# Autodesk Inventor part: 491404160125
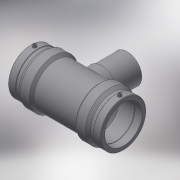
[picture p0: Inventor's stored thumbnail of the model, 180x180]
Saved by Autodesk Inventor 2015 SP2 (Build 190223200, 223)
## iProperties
Created: 2017-06
Part Number: 491404160125
Material: Generic
Description: PLASSON REDUCING TEE 160x125x160
Document SubType Name: Modeling
Designer: KIM
Mass: 5000.41 g
Surface Area: 5471.45 cm^2
Volume: 5000.41 cm^3
Density: 1 g/cm^3
Appearance: Default
Author: KIM
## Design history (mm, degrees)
derived "491404.ipt"
feature "Solid1::491404.ipt"
tag "TaggingFeature1"
body "Solid1"
other parameters: "d0" = 396, "d2" = 209, "d3" = 97, "d4" = 79.2, "d5" = 188.1, "d6" = 152, "d8" = 168 deg, "d10" = 38.8, "d11" = 12.93333, "d13" = 396, "d14" = 17.6296, "d17" = 144, "d19" = 3.52592, "d20" = 168 deg, "d22" = 194.37, "d23" = 209, "d25" = 135 deg, "d26" = 277.2, "d29" = 105, "d30" = 15, "d31" = 158.4, "d34" = 5 deg, "d35" = 15, "d39" = 5 deg, "d41" = 4, "d42" = 14, "d43" = 0, "d45" = 4, "d46" = 6, "d47" = 0, "d48" = -214, "d49" = 125, "d51" = 0, "d54" = 0, "d55" = 188.1, "d56" = 209, "d57" = 138.6, "d58" = 135 deg, "d59" = 97, "d60" = 97, "d61" = 135 deg, "d62" = 214, "d72" = 180.18, "d73" = 90.09, "d74" = -214, "d75" = 131.25, "d77" = 0, "d80" = 0, "d81" = 125, "d82" = 109.5, "d83" = 0, "d84" = 3, "d85" = 0, "d86" = 32.33333, "d87" = 190.4826, "d88" = 12.93333, "d89" = 3, "d90" = 0, "L_" = 396, "L_1" = 97, "D_" = 209, "A_" = 105, "d_2" = 12, "H_" = 214, "d_1" = 125
